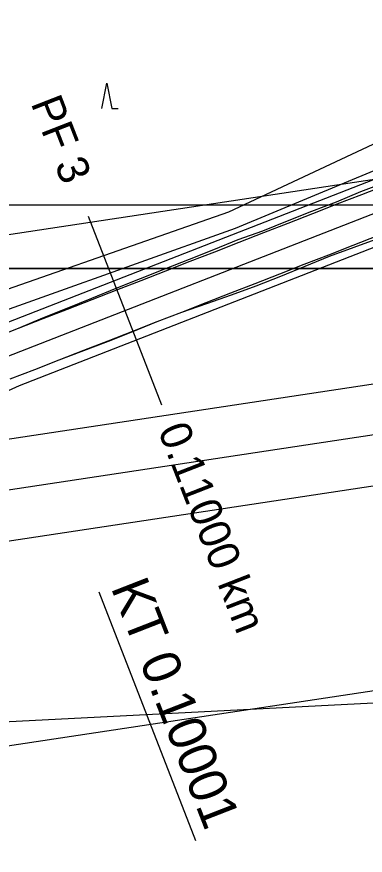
# Model space of a CAD drawing. Extents: x -555887 to -552101, y -1100251 to -1096546.
# Drawn here: x -554093.6 to -554065.9, y -1096817.1 to -1096750.8 of the extents above; entities that cross this region are included whole.
import ezdxf

# ---------------------------------------------------------------- set-up
doc = ezdxf.new("R2010")
doc.units = 0
for name, color, linetype in [('07_OCH_P A POPISY TI', 7, 'Continuous'), ('07_PLYNOVOD', 7, 'Continuous'), ('PARCELY_cesty', 7, 'Continuous'), ('POLYGONY_SITUACE_PF', 7, 'Continuous'), ('POLYGONY_SITUACE_PF_POPISY', 7, 'Continuous'), ('POLYGONY_SITUACE_PO', 7, 'Continuous'), ('ram_VC6', 7, 'Continuous'), ('vrstevnice', 7, 'Continuous'), ('ZSST', 7, 'Continuous')]:
    doc.layers.add(name, color=color, linetype=linetype)

msp = doc.modelspace()

# ---------------------------------------------------------------- linework, layer by layer
msp.add_line((-554087.055, -1096796.32), (-554079.401, -1096815.975))
at = {"layer": '07_OCH_P A POPISY TI'}
msp.add_lwpolyline([(-554130.516, -1096773.525), (-554061.917, -1096763.171), (-553969.228, -1096749.349), (-553879.887, -1096736.04), (-553864.66, -1096733.645), (-553882.5, -1096776.871), (-553963.332, -1096788.911), (-554055.983, -1096802.729), (-554135.075, -1096814.666)], dxfattribs=at)
msp.add_lwpolyline([(-554152.604, -1096784.878), (-554208.413, -1096768.467), (-554202.277, -1096761.933), (-554150.138, -1096777.264), (-554149.469, -1096777.303), (-554148.05, -1096777.984), (-554147.522, -1096778.568), (-554137.256, -1096789.931), (-554136.597, -1096790.624), (-554059.543, -1096778.994), (-553966.87, -1096765.174), (-553877.465, -1096751.856), (-553871.809, -1096750.966), (-553875.383, -1096759.627), (-553876.255, -1096759.764), (-553965.69, -1096773.086), (-554058.357, -1096786.906), (-554137.463, -1096798.845), (-554137.94, -1096798.917), (-554138.901, -1096798.83), (-554139.814, -1096798.517), (-554140.626, -1096797.996), (-554140.959, -1096797.646), (-554143.124, -1096795.369)], close=True, dxfattribs=at)
at = {"layer": '07_PLYNOVOD'}
msp.add_lwpolyline([(-553873.596, -1096755.297), (-553876.86, -1096755.81), (-553966.28, -1096769.13), (-554058.95, -1096782.95), (-554138.06, -1096794.89), (-554140.19, -1096792.65), (-554150.49, -1096781.25), (-554150.83, -1096781.23), (-554205.345, -1096765.2)], dxfattribs=at)
at = {"layer": 'PARCELY_cesty'}
for points in [[(-554174.9, -1096838.86), (-554167.64, -1096831.88), (-554135.583, -1096801.115), (-554129.606, -1096795.741), (-554116.704, -1096786.258), (-554106.195, -1096780.331), (-554095.284, -1096775.378), (-554029.882, -1096749.909), (-554024.308, -1096746.797), (-554020.974, -1096743.614), (-554018.176, -1096739.734), (-554005.148, -1096716.478), (-553996.738, -1096709.171), (-553992.165, -1096705.876), (-553986.987, -1096703.39), (-553981.451, -1096701.854), (-553975.732, -1096701.317), (-553970.007, -1096701.795), (-553964.395, -1096703.289), (-553952.141, -1096709.778)], [(-554168.999, -1096840.134), (-554132.179, -1096804.778), (-554126.446, -1096799.624), (-554113.985, -1096790.465), (-554103.93, -1096784.793), (-554093.342, -1096779.988), (-554027.746, -1096754.443), (-554021.315, -1096750.852), (-554017.188, -1096746.913), (-554013.953, -1096742.427), (-554001.212, -1096719.682), (-553993.63, -1096713.095), (-553989.602, -1096710.191), (-553985.223, -1096708.089), (-553980.542, -1096706.791), (-553975.706, -1096706.337), (-553970.865, -1096706.741), (-553966.232, -1096707.974), (-553954.851, -1096714.001)]]:
    msp.add_lwpolyline(points, dxfattribs=at)
at = {"layer": 'POLYGONY_SITUACE_PF'}
for p, q in [((-554087.909, -1096766.604), (-554085.006, -1096774.059)), ((-554085.006, -1096774.059), (-554082.103, -1096781.513))]:
    msp.add_line(p, q, dxfattribs=at)
at = {"layer": 'POLYGONY_SITUACE_PO'}
for p, q in [((-554094.313, -1096777.683), (-554028.814, -1096752.176)), ((-554066.311, -1096764.653), (-554064.366, -1096763.906)), ((-554066.227, -1096764.868), (-554064.286, -1096764.112)), ((-554066.227, -1096764.868), (-554064.286, -1096764.112)), ((-554068.237, -1096765.449), (-554066.311, -1096764.653)), ((-554070.178, -1096766.205), (-554068.237, -1096765.449)), ((-554068.169, -1096765.624), (-554066.227, -1096764.868)), ((-554068.169, -1096765.624), (-554066.227, -1096764.868)), ((-554070.11, -1096766.38), (-554068.169, -1096765.624)), ((-554070.11, -1096766.38), (-554068.169, -1096765.624)), ((-554072.116, -1096766.97), (-554070.178, -1096766.205)), ((-554072.051, -1096767.136), (-554070.11, -1096766.38)), ((-554072.051, -1096767.136), (-554070.11, -1096766.38)), ((-554074.05, -1096767.745), (-554072.116, -1096766.97)), ((-554073.993, -1096767.892), (-554072.051, -1096767.136)), ((-554073.993, -1096767.892), (-554072.051, -1096767.136)), ((-554076.011, -1096768.45), (-554074.05, -1096767.745)), ((-554075.934, -1096768.648), (-554073.993, -1096767.892)), ((-554075.934, -1096768.648), (-554073.993, -1096767.892)), ((-554066.899, -1096768.885), (-554064.957, -1096768.129)), ((-554066.899, -1096768.885), (-554064.957, -1096768.129)), ((-554077.945, -1096769.226), (-554076.011, -1096768.45)), ((-554077.875, -1096769.404), (-554075.934, -1096768.648)), ((-554077.875, -1096769.404), (-554075.934, -1096768.648)), ((-554066.836, -1096769.047), (-554064.88, -1096768.329)), ((-554079.883, -1096769.989), (-554077.945, -1096769.226)), ((-554079.817, -1096770.16), (-554077.875, -1096769.404)), ((-554079.817, -1096770.16), (-554077.875, -1096769.404)), ((-554068.84, -1096769.641), (-554066.899, -1096768.885)), ((-554068.84, -1096769.641), (-554066.899, -1096768.885)), ((-554068.792, -1096769.765), (-554066.836, -1096769.047)), ((-554081.814, -1096770.771), (-554079.883, -1096769.989)), ((-554070.781, -1096770.397), (-554068.84, -1096769.641)), ((-554070.781, -1096770.397), (-554068.84, -1096769.641)), ((-554070.719, -1096770.556), (-554068.792, -1096769.765)), ((-554083.758, -1096771.52), (-554081.814, -1096770.771)), ((-554081.758, -1096770.916), (-554079.817, -1096770.16)), ((-554081.758, -1096770.916), (-554079.817, -1096770.16)), ((-554072.723, -1096771.153), (-554070.781, -1096770.397)), ((-554072.723, -1096771.153), (-554070.781, -1096770.397)), ((-554072.648, -1096771.344), (-554070.719, -1096770.556)), ((-554083.699, -1096771.672), (-554081.758, -1096770.916)), ((-554083.699, -1096771.672), (-554081.758, -1096770.916)), ((-554074.664, -1096771.909), (-554072.723, -1096771.153)), ((-554074.664, -1096771.909), (-554072.723, -1096771.153)), ((-554074.584, -1096772.113), (-554072.648, -1096771.344)), ((-554085.69, -1096772.3), (-554083.758, -1096771.52)), ((-554085.641, -1096772.428), (-554083.699, -1096771.672)), ((-554085.641, -1096772.428), (-554083.699, -1096771.672)), ((-554076.605, -1096772.665), (-554074.664, -1096771.909)), ((-554076.605, -1096772.665), (-554074.664, -1096771.909)), ((-554076.547, -1096772.815), (-554074.584, -1096772.113)), ((-554087.618, -1096773.09), (-554085.69, -1096772.3)), ((-554087.582, -1096773.184), (-554085.641, -1096772.428)), ((-554087.582, -1096773.184), (-554085.641, -1096772.428)), ((-554078.547, -1096773.421), (-554076.605, -1096772.665)), ((-554078.547, -1096773.421), (-554076.605, -1096772.665)), ((-554089.552, -1096773.866), (-554087.618, -1096773.09)), ((-554089.523, -1096773.94), (-554087.582, -1096773.184)), ((-554089.523, -1096773.94), (-554087.582, -1096773.184)), ((-554080.488, -1096774.177), (-554078.547, -1096773.421)), ((-554080.488, -1096774.177), (-554078.547, -1096773.421)), ((-554078.511, -1096773.513), (-554076.547, -1096772.815)), ((-554091.489, -1096774.633), (-554089.552, -1096773.866)), ((-554091.465, -1096774.696), (-554089.523, -1096773.94)), ((-554091.465, -1096774.696), (-554089.523, -1096773.94)), ((-554080.483, -1096774.191), (-554078.511, -1096773.513)), ((-554093.411, -1096775.439), (-554091.489, -1096774.633)), ((-554093.406, -1096775.452), (-554091.465, -1096774.696)), ((-554093.406, -1096775.452), (-554091.465, -1096774.696)), ((-554082.429, -1096774.933), (-554080.488, -1096774.177)), ((-554082.429, -1096774.933), (-554080.488, -1096774.177)), ((-554082.429, -1096774.933), (-554080.483, -1096774.191)), ((-554095.352, -1096776.214), (-554093.406, -1096775.452)), ((-554095.352, -1096776.214), (-554093.406, -1096775.452)), ((-554094.217, -1096775.769), (-554093.411, -1096775.439)), ((-554084.371, -1096775.689), (-554082.429, -1096774.933)), ((-554084.371, -1096775.689), (-554082.429, -1096774.933)), ((-554084.365, -1096775.704), (-554082.429, -1096774.933)), ((-554082.429, -1096774.933), (-554082.429, -1096774.933)), ((-554082.429, -1096774.933), (-554082.429, -1096774.933)), ((-554086.312, -1096776.445), (-554084.371, -1096775.689)), ((-554086.312, -1096776.445), (-554084.371, -1096775.689)), ((-554086.298, -1096776.48), (-554084.365, -1096775.704)), ((-554088.253, -1096777.201), (-554086.312, -1096776.445)), ((-554088.253, -1096777.201), (-554086.312, -1096776.445)), ((-554088.248, -1096777.215), (-554086.298, -1096776.48)), ((-554090.195, -1096777.957), (-554088.253, -1096777.201)), ((-554090.195, -1096777.957), (-554088.253, -1096777.201)), ((-554090.195, -1096777.957), (-554088.248, -1096777.215)), ((-554092.136, -1096778.713), (-554090.195, -1096777.957)), ((-554092.136, -1096778.713), (-554090.195, -1096777.957)), ((-554092.136, -1096778.713), (-554090.195, -1096777.957)), ((-554090.195, -1096777.957), (-554090.195, -1096777.957)), ((-554094.07, -1096779.471), (-554092.136, -1096778.713)), ((-554094.07, -1096779.471), (-554092.136, -1096778.713)), ((-554094.07, -1096779.471), (-554092.136, -1096778.713))]:
    msp.add_line(p, q, dxfattribs=at)
at = {"layer": 'ram_VC6'}
for points in [[(-553956.64, -1096765.72), (-554313.64, -1096765.72), (-554313.64, -1097395.72), (-553956.64, -1097395.72)], [(-553961.64, -1096770.72), (-554308.64, -1096770.72), (-554308.64, -1097390.72), (-553961.64, -1097390.72)]]:
    msp.add_lwpolyline(points, close=True, dxfattribs=at)
for points in [[(-553956.64, -1096765.72), (-554313.64, -1096765.72), (-554313.64, -1097395.72), (-553956.64, -1097395.72), (-553956.64, -1096765.72)], [(-553956.64, -1096765.72), (-554313.64, -1096765.72), (-554313.64, -1097395.72), (-553956.64, -1097395.72), (-553956.64, -1096765.72)], [(-553961.64, -1097390.72), (-554308.64, -1097390.72), (-554308.64, -1096770.72), (-553961.64, -1096770.72), (-553961.64, -1097390.72)], [(-553961.64, -1097185.72), (-553961.64, -1097390.72), (-554308.64, -1097390.72), (-554308.64, -1096770.72), (-553961.64, -1096770.72), (-553961.64, -1096975.72), (-553961.64, -1097185.72)]]:
    msp.add_lwpolyline(points, dxfattribs=at)
at = {"layer": 'vrstevnice'}
msp.add_lwpolyline([(-554109.602, -1096807.348), (-554060.646, -1096804.854), (-554010.941, -1096802.859), (-553993.456, -1096800.365), (-553977.469, -1096796.05), (-553960.121, -1096788.769), (-553945.287, -1096782.242), (-553937.241, -1096775.463), (-553928.19, -1096763.915), (-553924.167, -1096755.881), (-553916.122, -1096742.073), (-553910.339, -1096729.019), (-553897.265, -1096712.7)], dxfattribs=at)
at = {"layer": 'ZSST'}
for p, q in [((-554086.819, -1096758.068), (-554086.408, -1096756.07)), ((-554086.408, -1096756.07), (-554086.019, -1096758.072)), ((-554086.019, -1096758.072), (-554085.519, -1096758.074))]:
    msp.add_line(p, q, dxfattribs=at)
for points in [[(-554009.12, -1096721.56), (-554015.18, -1096729.9), (-554024.59, -1096743.78), (-554029.87, -1096747.74), (-554036.85, -1096750.95), (-554054.31, -1096755.76), (-554076.78, -1096766.28), (-554100.4, -1096774.5), (-554109.57, -1096777.34), (-554130, -1096792.74), (-554141.88, -1096803.78), (-554155.75, -1096815.27)], [(-554160.46, -1096823.12), (-554154.41, -1096816.61), (-554141.11, -1096804.53), (-554129.31, -1096793.72), (-554108.05, -1096779.54), (-554099.77, -1096775.93), (-554076.23, -1096767.55), (-554053.62, -1096758.15), (-554036.85, -1096750.95)]]:
    msp.add_lwpolyline(points, dxfattribs=at)

# ---------------------------------------------------------------- texts
msp.add_text('KT 0.10001', height=3, rotation=291.27727).set_placement((-554086.124, -1096795.957))
at = {"layer": 'POLYGONY_SITUACE_PF_POPISY'}
for s, p in [('PF 3', (-554092.469, -1096757.649)), ('0.11000 km', (-554082.398, -1096783.51))]:
    msp.add_text(s, height=2.5, rotation=291.27727, dxfattribs=at).set_placement(p)

doc.saveas('drawing.dxf')
